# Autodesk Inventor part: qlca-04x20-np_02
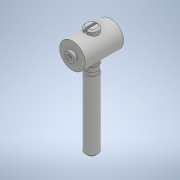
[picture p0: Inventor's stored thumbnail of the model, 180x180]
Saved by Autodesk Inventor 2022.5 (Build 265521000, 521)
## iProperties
Part Number: qlca-04x20-np_02
Material: 一般
Document SubType Name: Modeling
Designer: ImaoCorp
Density: 1 g/cm^3
Appearance: 既定
Author: ImaoCorp
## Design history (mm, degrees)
feature "qlca-04x20-np_02"
node "ソリッド1"
